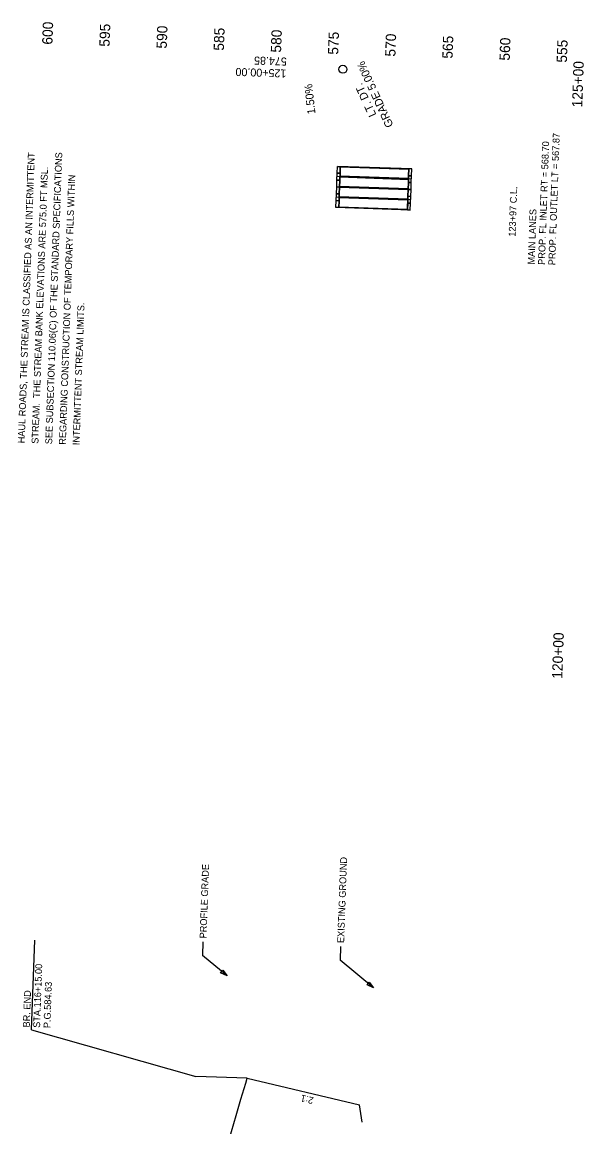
# Model space of a CAD drawing. Extents: x 634032 to 635126, y 289804 to 291423.
# Drawn here: x 634635 to 635126, y 290420 to 291386 of the extents above; entities that cross this region are included whole.
import ezdxf

# ---------------------------------------------------------------- set-up
doc = ezdxf.new("R2010")
doc.units = 0
for name, color, linetype in [('30', 7, 'Continuous'), ('Level 24', 7, 'Continuous'), ('R_Dimension', 7, 'Continuous'), ('R_Draft', 7, 'Continuous'), ('R_Vert Alg', 7, 'Continuous'), ('R_Vert Alg Annot', 7, 'Continuous'), ('S_CROSS_DRAIN', 7, 'Continuous')]:
    doc.layers.add(name, color=color, linetype=linetype)

msp = doc.modelspace()

# ---------------------------------------------------------------- linework, layer by layer
at = {"layer": 'R_Dimension'}
for p, q in [((634975.08, 291257.99), (634910.12, 291260.26)), ((634972.29, 291249.58), (634912.32, 291251.68)), ((634972.56, 291257.58), (634912.6, 291259.67)), ((634972.16, 291246.09), (634972.37, 291252.08)), ((634972.37, 291252.08), (634972.58, 291258.08)), ((634974.45, 291240), (634909.49, 291242.27)), ((634974.77, 291249), (634909.81, 291251.26)), ((634971.97, 291240.59), (634912.01, 291242.68)), ((634972.25, 291248.58), (634912.29, 291250.68)), ((634971.95, 291240.09), (634972.16, 291246.09)), ((634974.14, 291231.01), (634909.18, 291233.28)), ((634971.62, 291230.59), (634911.66, 291232.69)), ((634971.66, 291231.59), (634911.69, 291233.69)), ((634971.94, 291239.59), (634911.97, 291241.68)), ((634971.54, 291228.1), (634971.74, 291234.09)), ((634971.74, 291234.09), (634971.95, 291240.09)), ((634973.82, 291222.01), (634908.86, 291224.28)), ((634973.82, 291222.01), (634908.86, 291224.28)), ((634973.82, 291222.01), (634908.86, 291224.28)), ((634971.34, 291222.6), (634911.38, 291224.69)), ((634971.33, 291222.1), (634971.54, 291228.1)), ((634642.81, 290505.2), (634645.54, 290583.61)), ((634792.55, 290582.1), (634792.14, 290570.11)), ((634912.86, 290578.03), (634912.44, 290566.04)), ((634813.62, 290552.24), (634792.14, 290570.11)), ((634941.63, 290541.76), (634912.44, 290566.04)), ((634642.81, 290505.2), (634786.35, 290464.3))]:
    msp.add_line(p, q, dxfattribs=at)
for points in [[(634809.96, 290557.23), (634813.62, 290552.24), (634808.04, 290554.93)], [(634937.98, 290546.75), (634941.63, 290541.76), (634936.06, 290544.44)]]:
    msp.add_lwpolyline(points, close=True, dxfattribs=at)
at = {"layer": 'R_Vert Alg'}
msp.add_line((634831.32, 290462.73), (634786.35, 290464.3), dxfattribs=at)
for points in [[(634792.68, 290314.72), (634793.34, 290317.93), (634796.41, 290332), (634799.61, 290346.06), (634802.94, 290360.12), (634806.4, 290374.17), (634810, 290388.22), (634813.72, 290402.27), (634817.59, 290416.31), (634821.58, 290430.34), (634825.71, 290444.37), (634829.97, 290458.4), (634831.32, 290462.73)], [(634831.32, 290462.73), (634929.39, 290439.53)], [(634931.89, 290424.28), (634929.39, 290439.53)]]:
    msp.add_lwpolyline(points, dxfattribs=at)
msp.add_circle((634914.89, 291345.14), 3.5, dxfattribs=at)
at = {"layer": 'S_CROSS_DRAIN'}
for p, q in [((634909.7, 291248.27), (634909.91, 291254.26)), ((634909.91, 291254.26), (634910.12, 291260.26)), ((634912.2, 291248.18), (634912.41, 291254.18)), ((634912.41, 291254.18), (634912.62, 291260.17)), ((634972.39, 291252.58), (634972.56, 291257.58)), ((634974.66, 291246), (634974.87, 291251.99)), ((634974.87, 291251.99), (634975.08, 291257.99)), ((634909.28, 291236.27), (634909.49, 291242.27)), ((634909.49, 291242.27), (634909.7, 291248.27)), ((634911.78, 291236.19), (634911.99, 291242.18)), ((634911.99, 291242.18), (634912.2, 291248.18)), ((634971.97, 291240.59), (634972.15, 291245.59)), ((634972.18, 291246.58), (634972.36, 291251.58)), ((634974.45, 291240), (634974.66, 291246)), ((634909.07, 291230.28), (634909.28, 291236.27)), ((634911.57, 291230.19), (634911.78, 291236.19)), ((634971.55, 291228.6), (634971.73, 291233.59)), ((634971.76, 291234.59), (634971.94, 291239.59)), ((634974.03, 291228.01), (634974.24, 291234.01)), ((634974.24, 291234.01), (634974.45, 291240)), ((634908.86, 291224.28), (634909.07, 291230.28)), ((634911.36, 291224.19), (634911.57, 291230.19)), ((634971.34, 291222.6), (634971.52, 291227.6)), ((634973.82, 291222.01), (634974.03, 291228.01))]:
    msp.add_line(p, q, dxfattribs=at)
for points in [[(634909.7, 291248.27), (634909.91, 291254.26), (634912.41, 291254.18), (634912.2, 291248.18)], [(634909.91, 291254.26), (634910.12, 291260.26), (634912.62, 291260.17), (634912.41, 291254.18)], [(634974.66, 291246), (634974.87, 291251.99), (634972.37, 291252.08), (634972.16, 291246.09)], [(634974.87, 291251.99), (634975.08, 291257.99), (634972.58, 291258.08), (634972.37, 291252.08)], [(634909.28, 291236.27), (634909.49, 291242.27), (634911.99, 291242.18), (634911.78, 291236.19)], [(634909.49, 291242.27), (634909.7, 291248.27), (634912.2, 291248.18), (634911.99, 291242.18)], [(634974.45, 291240), (634974.66, 291246), (634972.16, 291246.09), (634971.95, 291240.09)], [(634909.07, 291230.28), (634909.28, 291236.27), (634911.78, 291236.19), (634911.57, 291230.19)], [(634974.03, 291228.01), (634974.24, 291234.01), (634971.74, 291234.09), (634971.54, 291228.1)], [(634974.24, 291234.01), (634974.45, 291240), (634971.95, 291240.09), (634971.74, 291234.09)], [(634908.86, 291224.28), (634909.07, 291230.28), (634911.57, 291230.19), (634911.36, 291224.19)], [(634973.82, 291222.01), (634974.03, 291228.01), (634971.54, 291228.1), (634971.33, 291222.1)]]:
    msp.add_lwpolyline(points, close=True, dxfattribs=at)

# ---------------------------------------------------------------- texts
at = {"layer": '30'}
for s, p in [('600', (634660.97, 291366.59)), ('595', (634710.94, 291364.76)), ('590', (634760.91, 291363.1)), ('585', (634810.88, 291361.27)), ('580', (634860.85, 291359.61)), ('575', (634910.82, 291357.78)), ('570', (634960.79, 291356.12)), ('565', (635010.76, 291354.29)), ('560', (635060.73, 291352.63)), ('555', (635110.7, 291350.8)), ('125+00', (635124.1, 291311.71)), ('120+00', (635106.65, 290812.02))]:
    msp.add_text(s, height=9, rotation=88, dxfattribs=at).set_placement(p)
at = {"layer": 'Level 24'}
for s, rotation, p in [('PROP. FL INLET RT = 568.70', 88.0044, (635091.46, 291174.02)), ('PROP. FL OUTLET LT = 567.87', 88.0044, (635100.45, 291173.71)), ('123+97 C.L.', 88.0044, (635065.78, 291198.66)), ('MAIN LANES', 88.0044, (635082.46, 291174.33)), ('STA.116+15.00', 88.0044, (634650.17, 290506.8)), ('P.G.584.63', 88.0044, (634659.16, 290506.49)), ('BR. END', 88.0044, (634641.18, 290507.11)), ('2:1', 166.69447, (634889.69, 290445.87))]:
    msp.add_text(s, height=6, rotation=rotation, dxfattribs=at).set_placement(p)
at = {"layer": 'R_Dimension'}
for s, p in [('EXISTING GROUND', (634915.96, 290580.92)), ('PROFILE GRADE', (634795.66, 290584.99))]:
    msp.add_text(s, height=6, rotation=88, dxfattribs=at).set_placement(p)
at = {"layer": 'R_Draft'}
for s, p in [('HAUL ROADS, THE STREAM IS CLASSIFIED AS AN INTERMITTENT', (634636.73, 291017.98)), ('SEE SUBSECTION 110.06(C) OF THE STANDARD SPECIFICATIONS', (634660.71, 291017.15)), ('STREAM.  THE STREAM BANK ELEVATIONS ARE 575.0 FT MSL.', (634648.72, 291017.57)), ('REGARDING CONSTRUCTION OF TEMPORARY FILLS WITHIN', (634672.71, 291016.73)), ('INTERMITTENT STREAM LIMITS.', (634684.7, 291016.31))]:
    msp.add_text(s, height=6, rotation=88, dxfattribs=at).set_placement(p)
at = {"layer": 'R_Vert Alg Annot'}
for s, rotation, p in [('574.85', 178, (634866, 291355.35)), ('GRADE 5.00%', 114.56505, (634959.28, 291296.16)), ('125+00.00', 178, (634865.64, 291344.86)), ('1.50%', 96.47241, (634891.01, 291306.22)), ('LT. DT.', 114.56505, (634944.34, 291305.37))]:
    msp.add_text(s, height=7, rotation=rotation, dxfattribs=at).set_placement(p)

doc.saveas('drawing.dxf')
